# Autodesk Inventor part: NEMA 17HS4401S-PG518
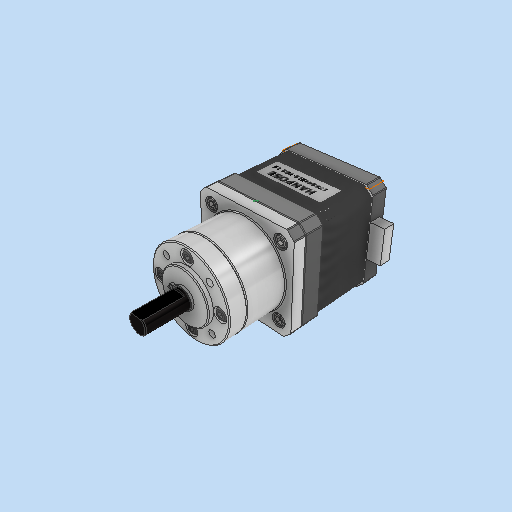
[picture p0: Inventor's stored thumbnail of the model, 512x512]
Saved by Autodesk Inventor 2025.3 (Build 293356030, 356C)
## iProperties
GlobalPropertyList: <PropertyList/>
Created: 2012-11
Part Number: NEMA 17HS4401S-PG518
Material: Rozsdamentes acél
Document SubType Name: Modeling
Designer: Romolicz Péter
Density: 8.08 g/cm^3
Mass: 635.188 g
Surface Area: 148.432 cm^2
Volume: 78.6123 cm^3
Appearance: Krómozott tengely
d0: 7.000 mm
d1: 22.000 mm
d4: 5.000 mm
d5: 31.000 mm
d6: 31.000 mm
d9: 3.000 mm
d10: 3.000 mm
d11: 3.000 mm
d12: 3.000 mm
d39: 42.000 mm
d40: 42.000 mm
d41: 135.00 deg
d42: 55.154 mm
d43: 55.154 mm
d44: 27.577 mm
d45: 27.577 mm
d46: 24.000 mm
d47: 0.00 deg
d48: 2.000 mm
d49: 0.00 deg
d50: 40,700 mm
d51: 0.00 deg
d60: -8,000 mm
d126: 25,000 mm
d127: 0.00 deg
d128: 1.000 mm
d129: 1.000 mm
d130: 1.000 mm
d131: 1.000 mm
d132: 0.500 mm
d134: 0.500 mm
d135: 0.500 mm
d136: 0.500 mm
d137: 0.500 mm
d138: 1.000 mm
d139: 1.000 mm
d140: 0.500 mm
d141: 0.00 deg
d145: 0.125 mm
d148: 56.000 ul
d150: 0.500 mm
d187: 40,000 mm
d188: 0.00 deg
d189: 47.000 mm
d190: 0.00 deg
d191: 0,600 mm
d192: 1.000 mm
d193: 0.500 mm
d196: 0.500 mm
d197: 1.200 mm
d198: 4.000 ul
d200: 1.200 mm
d205: 2.500 mm
d206: 2.500 mm
d207: 1.000 mm
d208: 0.00 deg
d209: 0.300 mm
d210: 10.000 mm
d211: 0.00 deg
d212: 10.000 mm
d213: 0.00 deg
d214: 10.000 mm
d215: 0.00 deg
d216: 10.000 mm
d217: 0.00 deg
d218: 0.200 mm
d219: 5.000 mm
d220: 0.00 deg
d221: 0.00 deg
Author: Romolicz Péter
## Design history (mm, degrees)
node "Annotazioni"
  node "Quota lineare 1" dims "d39" = 42, "d40" = 42, angle "d41" = 135 deg, "d42" = 55.154 (derived), "d43" = 55.154, "d44" = 27.577 (derived), "d45" = 27.577 (derived), "d294" = 45.7 (derived)
  node "Quota lineare 2" dims "d39" = 42, "d40" = 42, angle "d41" = 135 deg, "d42" = 55.154 (derived), "d43" = 55.154, "d44" = 27.577 (derived), "d45" = 27.577 (derived), "d297" = 42 (derived)
  node "Quota lineare 3" dims "d39" = 42, "d40" = 42, angle "d41" = 135 deg, "d42" = 55.154 (derived), "d43" = 55.154, "d44" = 27.577 (derived), "d45" = 27.577 (derived), "d300" = 42 (derived)
  node "Quota diametro 1" dims "d39" = 42, "d40" = 42, angle "d41" = 135 deg, "d42" = 55.154 (derived), "d43" = 55.154, "d44" = 27.577 (derived), "d45" = 27.577 (derived), "d302" = 36 (derived)
  node "Quota lineare 4" dims "d39" = 42, "d40" = 42, angle "d41" = 135 deg, "d42" = 55.154 (derived), "d43" = 55.154, "d44" = 27.577 (derived), "d45" = 27.577 (derived), "d305" = 18 (derived)
  node "Quota lineare 5" dims "d39" = 42, "d40" = 42, angle "d41" = 135 deg, "d42" = 55.154 (derived), "d43" = 55.154, "d44" = 27.577 (derived), "d45" = 27.577 (derived), "d308" = 2 (derived)
  node "Quota lineare 6" dims "d39" = 42, "d40" = 42, angle "d41" = 135 deg, "d42" = 55.154 (derived), "d43" = 55.154, "d44" = 27.577 (derived), "d45" = 27.577 (derived), "d311" = 24 (derived)
sketch "Sketch1"
  geometry: L1 (-15.5, 15.5)-(15.5, 15.5); L2 (15.5, 15.5)-(15.5, -15.5); L3 (15.5, -15.5)-(-15.5, -15.5); L4 (-15.5, -15.5)-(-15.5, 15.5); L5 (-21, 21)-(21, 21); L6 (21, 21)-(21, -21); L7 (21, -21)-(-21, -21); L8 (-21, -21)-(-21, 21); L9 (-21, 18)-(-18, 21); L10 (21, 18)-(18, 21); L11 (-21, -18)-(-18, -21); L12 (21, -18)-(18, -21); L13 (-21, 18)-(-21, -18); L14 (-18, -21)-(18, -21); L15 (21, -18)-(21, 18); L16 (18, 21)-(-18, 21); C1 r 3.5 at (0, 0); C2 r 11 at (0, 0); C3 r 2.5 at (0, 0); C4 r 1.5 at (-15.5, 15.5); C5 r 1.5 at (15.5, 15.5); C6 r 1.5 at (-15.5, -15.5); C7 r 1.5 at (15.5, -15.5); 5 further points
  constraints: 32 end point, 8 point on line, 7 centre point, 6 coincident, 5 parallel, 4 collinear, 4 midpoint, 4 perpendicular, 2 horizontal, 2 horizontal alignment, 2 vertical alignment, 1 concentric
  dimensions: "d0" = 7 diameter of C1; "d1" = 22 diameter of C2; "d4" = 5 diameter of C3; "d5" = 31 distance of L2.end L3.end; "d6" = 31 distance of L1.end L2.end; "d9" = 3 diameter of C4; "d10" = 3 diameter of C5; "d11" = 3 diameter of C6; "d12" = 3 diameter of C7; "d39" = 42 distance of L6.end L7.end; "d40" = 42 distance of L5.end L6.end; "d41" = 135 deg angle of L10 L6; "d42" = 55.154 distance between parallel lines of L10 L11 (derived); "d43" = 55.154 distance between parallel lines of L12 L9; "d44" = 27.577 distance from line of point (0, 0) L10 (derived); "d45" = 27.577 distance from line of point (0, 0) L12 (derived)
extrude "Extrusion1" new body sketch "Sketch1" distance "d46" = 24; taper "d47" = 0 deg; dims "d187" = 40, angle "d188" = 0 deg
extrude "Extrusion2" join sketch "Sketch1" distance "d48" = 2; taper "d49" = 0 deg
extrude "Extrusion3" join sketch "Sketch1" distance "d50" = 40.7; taper "d51" = 0 deg
workplane "Work Plane2"
sketch "Sketch4"
  geometry: L1 (-21, 18)-(-18, 21) reference; L2 (-21, 18)-(-18, 21) reference; L3 (-21, -18)-(-21, 18) reference; L4 (-18, -21)-(-21, -18) reference; L5 (18, -21)-(-18, -21) reference; L6 (21, -18)-(18, -21) reference; L7 (21, 18)-(21, -18) reference; L8 (18, 21)-(21, 18) reference; L9 (-18, 21)-(18, 21) reference; C1 r 1.5 at (-15.5, 15.5) reference; C2 r 1.5 at (-15.5, -15.5) reference; C3 r 1.5 at (15.5, 15.5) reference; C4 r 1.5 at (15.5, -15.5) reference; C5 r 11 at (0, 0) reference; 1 further point
extrude "Extrusion7" cut sketch "Sketch4" distance "d126" = 25; taper "d127" = 0 deg
sketch "Sketch5"
  geometry: L1 (-21, -18)-(-21, 18) reference; L2 (-18, -21)-(-21, -18) reference; L3 (18, -21)-(-18, -21) reference; L4 (21, -18)-(18, -21) reference; L5 (21, 18)-(21, -18) reference; L6 (18, 21)-(21, 18) reference; L7 (-18, 21)-(18, 21) reference; L8 (-21, 18)-(-18, 21) reference; L9 (-17.086, 20.5)-(-20.5, 17.086); L10 (-20.5, -17.086)-(-17.086, -20.5); L11 (-18, -21)-(-21, -18) reference; L12 (21, -18)-(18, -21) reference; L13 (18, 21)-(21, 18) reference; L14 (-21, 18)-(-18, 21) reference; L15 (20.5, -17.086)-(20.5, 17.086); L16 (17.086, 20.5)-(-17.086, 20.5); L17 (-20.5, 17.086)-(-20.5, -17.086); L18 (-17.086, -20.5)-(17.086, -20.5); L19 (17.086, -20.5)-(20.5, -17.086); L20 (20.5, 17.086)-(17.086, 20.5); C1 r 11 at (0, 0) reference; C2 r 1.5 at (15.5, -15.5) reference; C3 r 1.5 at (15.5, 15.5) reference; C4 r 1.5 at (-15.5, -15.5) reference; C5 r 1.5 at (-15.5, 15.5) reference
  constraints: 16 end point, 5 parallel
  dimensions: "d128" = 1 distance between parallel lines of L10 L2; "d131" = 1 distance between parallel lines of L8 L9; "d132" = 0.5 distance between parallel lines of L1 L17; "d134" = 0.5 distance between parallel lines of L5 L15; "d135" = 0.5 distance between parallel lines of L7 L16; "d137" = 0.5 distance between parallel lines of L18 L3; "d138" = 1 distance between parallel lines of L4 L19; "d139" = 1 distance between parallel lines of L6 L20
extrude "Extrusion8" join sketch "Sketch5" distance "d140" = 0.5; taper "d141" = 0 deg
chamfer "Chamfer1" distance "d145" = 0.125; stored, may be unused: second distance "d146" = 2, angle "d147" = 45 deg
extrude "Extrusion9" join sketch "Sketch1" distance "d189" = 47; taper "d190" = 0 deg
fillet "Fillet1" dims "d191" = 0.6
fillet "Fillet2" dims "d192" = 1
chamfer "Chamfer2" distance "d193" = 0.5; stored, may be unused: second distance "d194" = 2, angle "d195" = 45 deg
fillet "Fillet3" dims "d196" = 0.5
sketch "Sketch6" dims "d205" = 2.5
  geometry: L1 (35.502, 0)-(0, 0) reference; L2 (35.502, -7.1)-(0, -7.1) reference; C1 r 0.6 at (15.951, -2.5); C2 r 0.6 at (19.551, -2.5); 6 further points; 2 other entities
  constraints: 4 horizontal, 2 centre point, 2 horizontal alignment, 1 coincident, 1 midpoint, 1 vertical alignment, 13 other
  dimensions: "d197" = 1.2 diameter of C1; "d200" = 1.2 distance of C1.centre point (17.151, -2.5); "d206" = 2.5 distance from line of L1 point (17.751, -2.5)
  node "Schizzo - Serie rettangolare1" dims "d200" = 1.2, "d203" = 10
extrude "Extrusion10" join sketch "Sketch6" distance "d207" = 1; taper "d208" = 0 deg
fillet "Fillet4" dims "d209" = 0.3
extrude "Extrusion11" join sketch "Sketch6" distance "d210" = 10; taper "d211" = 0 deg
extrude "Extrusion12" join sketch "Sketch6" distance "d212" = 10; taper "d213" = 0 deg
extrude "Extrusion13" join sketch "Sketch6" distance "d214" = 10; taper "d215" = 0 deg
extrude "Extrusion14" join sketch "Sketch6" distance "d216" = 10; taper "d217" = 0 deg
extrude "Extrusion15" join sketch "Sketch6" distance "d218" = 0.2; taper "d220" = 0 deg; dims "d219" = 5, angle "d221" = 0 deg
sketch "Sketch11"
  geometry: L1 (20.5, 17.793)-(17.793, 20.5); L2 (20.5, 17.793)-(17.793, 20.5); L3 (2.875, 14)-(2.875, 17.769); L4 (2.875, 14)-(2.875, 17.769); L5 (-17.793, -20.5)-(17.793, -20.5); L6 (-20.5, -17.793)-(-17.793, -20.5); L7 (-20.5, -17.793)-(-17.793, -20.5); L8 (-21, 21)-(21, -21); L9 (21, 21)-(-21, -21); L10 (-2.646, 3)-(2.646, 3); L11 (2.646, 3)-(-2.646, 3); L12 (17.793, -20.5)-(20.5, -17.793); L13 (17.793, -20.5)-(20.5, -17.793); L14 (0, 15.181)-(1.023, 14.59); L15 (1.023, 14.59)-(1.023, 13.41); L16 (1.023, 13.41)-(0, 12.819); L17 (-1.022, 14.59)-(0, 15.181); L18 (-1.022, 13.41)-(-1.022, 14.59); L19 (-1.022, 13.41)-(0, 12.819); L20 (0, 12.819)-(-1.022, 13.41); L21 (-2.875, 14)-(-2.875, 17.769); L22 (-14.022, 15.5)-(-14.761, 14.22); L23 (-14.761, 16.78)-(-14.022, 15.5); L24 (-14.761, 14.22)-(-16.239, 14.22); L25 (-16.239, 16.78)-(-14.761, 16.78); L26 (-16.978, 15.5)-(-16.239, 14.22); L27 (-16.239, 14.22)-(-16.978, 15.5); L28 (-16.978, 15.5)-(-16.239, 16.78); L29 (-18.293, 49.829)-(-21, 47.122); L30 (-21, 47.122)-(-47.122, 21); L31 (-14, 2.875)-(-17.769, 2.875); L32 (-14, 2.875)-(-17.769, 2.875); L33 (-13.41, 1.023)-(-12.819, 0); L34 (-13.41, -1.022)-(-14.59, -1.022); L35 (-13.41, -1.022)-(-12.819, 0); L36 (-12.819, 0)-(-13.41, -1.022); L37 (-14.59, 1.023)-(-13.41, 1.023); L38 (-15.181, 0)-(-14.59, 1.023); L39 (-14.59, -1.022)-(-15.181, 0); L40 (-14, -2.875)-(-17.769, -2.875); L41 (-15.5, -14.022)-(-14.22, -14.761); L42 (-16.78, -14.761)-(-15.5, -14.022); L43 (-14.22, -14.761)-(-14.22, -16.239); L44 (-15.5, -16.978)-(-14.22, -16.239); L45 (-14.22, -16.239)-(-15.5, -16.978); L46 (-15.5, -16.978)-(-16.78, -16.239); L47 (-16.78, -16.239)-(-16.78, -14.761); L48 (-2.875, -14)-(-2.875, -17.769); L49 (-2.875, -14)-(-2.875, -17.769); L50 (-1.023, -13.41)-(0, -12.819); L51 (1.022, -13.41)-(1.022, -14.59); L52 (1.022, -13.41)-(0, -12.819); L53 (0, -12.819)-(1.022, -13.41); L54 (-1.023, -14.59)-(-1.023, -13.41); L55 (0, -15.181)-(-1.023, -14.59); L56 (1.022, -14.59)-(0, -15.181); L57 (2.875, -14)-(2.875, -17.769); L58 (14.022, -15.5)-(14.761, -14.22); L59 (14.761, -16.78)-(14.022, -15.5); L60 (14.761, -14.22)-(16.239, -14.22); L61 (16.978, -15.5)-(16.239, -14.22); L62 (16.239, -14.22)-(16.978, -15.5); L63 (16.978, -15.5)-(16.239, -16.78); L64 (16.239, -16.78)-(14.761, -16.78)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; C1 r 11 at (0, 0); C2 r 4 at (0, 0); C3 r 1.84 at (0, 14); C4 r 2.34 at (0, 14); C5 r 2.34 at (0, 14); C6 r 1.5 at (-9.899, 9.899); C7 r 1.5 at (-9.899, 9.899); C8 r 2.34 at (-15.5, 15.5); C9 r 2.875 at (-15.5, 15.5); C10 r 1.84 at (-14, 0); C11 r 2.34 at (-14, 0); C12 r 2.34 at (-14, 0); C13 r 1.5 at (-9.899, -9.899); C14 r 2.34 at (-15.5, -15.5); C15 r 2.875 at (-15.5, -15.5); C16 r 1.84 at (0, -14); C17 r 2.34 at (0, -14); C18 r 2.34 at (0, -14); C19 r 1.5 at (9.899, -9.899); C20 r 2.34 at (15.5, -15.5); C21 r 2.875 at (15.5, -15.5); C22 r 1.84 at (14, 0); C23 r 2.34 at (14, 0); C24 r 2.34 at (14, 0); C25 r 1.5 at (9.899, 9.899); C26 r 2.34 at (15.5, 15.5); C27 r 2.875 at (15.5, 15.5); A1 r 4.5 centre (0, 0) between (3.139, 3.224) and (3.139, -3.224); A2 r 18 centre (0, 0) between (-2.875, 17.769) and (2.875, 17.769); A3 r 4 centre (0, 0) between (0.527, 3.965) and (0.554, 3.961); A4 r 2.875 centre (0, 14) between (-2.875, 14) and (2.875, 14); A5 r 2.875 centre (0, 14) between (-2.875, 14) and (2.875, 14); A6 r 2.875 centre (-14, 0) between (-14, -2.875) and (-14, 2.875); A7 r 2.875 centre (-14, 0) between (-14, -2.875) and (-14, 2.875); A8 r 2.875 centre (0, -14) between (2.875, -14) and (-2.875, -14); A9 r 2.875 centre (0, -14) between (2.875, -14) and (-2.875, -14); A10 r 2.875 centre (14, 0) between (14, 2.875) and (14, -2.875); A11 r 2.875 centre (14, 0) between (14, 2.875) and (14, -2.875); 32 further points; 4 other entities
  constraints: 162 end point, 38 centre point, 25 coincident, 13 point on circle, 4 collinear, 3 midpoint, 2 horizontal, 1 concentric, 1 perpendicular, 1 tangent, 1 vertical, 257 other
  dimensions: "d239" = 42 distance of L8.end L9.end; "d240" = 42 distance of L9.end L8.start; "d241" = 36 diameter of A2; "d242" = 22 diameter of C1; "d245" = 360 deg dimension on A1.centre L3.end (derived)
  node "Schizzo - Serie circolare1" dims "d245" = 360 deg (derived)
extrude "Extrusion16" join sketch "Sketch11" distance "d247" = 5; taper "d248" = 0 deg
extrude "Extrusion17" join sketch "Sketch11" stored distance "d249" = 24; taper "d250" = 0 deg
extrude "Extrusion18" cut sketch "Sketch11" stored distance "d251" = 6; taper "d252" = 0 deg
extrude "Extrusion19" cut sketch "Sketch11" stored distance "d253" = 3; taper "d254" = 0 deg
extrude "Extrusion20" join sketch "Sketch11" stored distance "d255" = 3; taper "d256" = 0 deg
extrude "Extrusion21" cut sketch "Sketch11" stored distance "d257" = 1.8; taper "d258" = 0 deg
extrude "Extrusion22" cut sketch "Sketch11" distance "d259" = 5; taper "d260" = 0 deg
extrude "Extrusion23" join sketch "Sketch11" distance "d261" = 5; taper "d262" = 0 deg
extrude "Extrusion24" cut sketch "Sketch11" stored distance "d263" = 1.5; taper "d264" = 0 deg
extrude "Extrusion25" join sketch "Sketch11" stored distance "d265" = 2; taper "d266" = 0 deg
extrude "Extrusion26" join sketch "Sketch11" stored distance "d267" = 3; taper "d268" = 0 deg
extrude "Extrusion27" join sketch "Sketch11" stored distance "d269" = 15; taper "d270" = 0 deg
fillet "Fillet5" dims "d271" = 0.5
fillet "Fillet6" dims "d272" = 0.3
fillet "Fillet7" dims "d273" = 0.5
chamfer "Chamfer3" distance "d274" = 0.4; stored, may be unused: second distance "d275" = 2, angle "d276" = 45 deg
chamfer "Chamfer4" distance "d277" = 0.4; stored, may be unused: second distance "d278" = 2, angle "d279" = 45 deg
chamfer "Chamfer5" distance "d280" = 0.4; stored, may be unused: second distance "d281" = 2, angle "d282" = 45 deg
sketch "Sketch12"
  geometry: L1 (3.929, -0.75)-(6.442, -0.75); L2 (5.481, -2.833)-(6.648, -1.142); L3 (6.648, -1.142)-(5.481, -2.833); L4 (3.837, -2.941)-(5.275, -2.941); L5 (5.275, -2.941)-(3.837, -2.941); L6 (0, 0)-(-1.45, 0); L7 (3.929, 0.75)-(6.442, 0.75); L8 (5.481, 2.833)-(6.648, 1.142); L9 (6.648, 1.142)-(5.481, 2.833); L10 (3.837, 2.941)-(5.275, 2.941); L11 (5.275, 2.941)-(3.837, 2.941); C1 r 0.8 at (4.837, -1.845); C2 r 0.8 at (4.837, -1.845); C3 r 4 at (0, 0); C4 r 0.8 at (4.837, 1.845); C5 r 0.8 at (4.837, 1.845); C6 r 0.8 at (4.837, 1.845); C7 r 0.8 at (4.837, 1.845); A1 r 0.25 centre (6.442, -1) between (6.648, -1.142) and (6.442, -0.75); A2 r 0.25 centre (6.442, -1) between (6.648, -1.142) and (6.442, -0.75); A3 r 0.25 centre (5.275, -2.691) between (5.275, -2.941) and (5.481, -2.833); A4 r 0.25 centre (5.275, -2.691) between (5.275, -2.941) and (5.481, -2.833); A5 r 4.5 centre (0, 0) between (3.139, 3.224) and (3.139, -3.224); A6 r 1 centre (3.837, -3.941) between (3.837, -2.941) and (3.139, -3.224); A7 r 1 centre (3.837, -3.941) between (3.837, -2.941) and (3.139, -3.224); A8 r 4 centre (0, 0) between (3.929, -0.75) and (3.929, 0.75); A9 r 1 centre (3.837, 3.941) between (3.139, 3.224) and (3.837, 2.941); A10 r 0.25 centre (6.442, 1) between (6.442, 0.75) and (6.648, 1.142); A11 r 0.25 centre (6.442, 1) between (6.442, 0.75) and (6.648, 1.142); A12 r 0.25 centre (5.275, 2.691) between (5.481, 2.833) and (5.275, 2.941); A13 r 0.25 centre (5.275, 2.691) between (5.481, 2.833) and (5.275, 2.941); 3 further points
  constraints: 27 point on circle, 22 end point, 20 centre point, 13 symmetric about line, 5 coincident, 2 collinear, 1 horizontal, 1 parallel, 7 other
extrude "Extrusion28" join sketch "Sketch12" distance "d283" = 1; taper "d284" = 0 deg
sketch "Sketch13"
  geometry: L1 (-18, 5.4)-(-18, 28.6) reference; L2 (-18, 5.4)-(-18, 21.4); L3 (-18, 21.4)-(-17.646, 21.754); L4 (-17.646, 21.754)-(-18, 22.107); L5 (-18, 21.4)-(-18, 22.107); L6 (0, -6.4)-(0, 38.4) reference; L7 (-18, 5.4)-(18, 5.4) reference; 1 further point
  constraints: 8 end point, 4 point on line, 1 collinear, 1 perpendicular
  dimensions: "d285" = 16 distance of L2.start L2.end; "d286" = 0.5 distance of L2.end L3.end; "d287" = 135 deg angle of L2 L3
revolve "Revolution1" sketch "Sketch13" stored, may be unused: angle "d288" = 90 deg
chamfer "Chamfer6" distance "d289" = 0.4; stored, may be unused: second distance "d290" = 2, angle "d291" = 45 deg
chamfer "Smusso7" distance "d312" = 3; stored, may be unused: second distance "d313" = 2, angle "d314" = 45 deg
sketch "Schizzo14"
  geometry: L1 (2.646, -3)-(-2.646, -3); C1 r 2 at (0, 0) reference; A1 r 4 centre (0, 0) between (2.646, -3) and (-2.646, -3); 1 further point
  constraints: 2 end point, 2 point on circle, 1 centre point, 1 coincident, 1 horizontal
  dimensions: "d315" = 8 diameter of A1; "d316" = 3 distance from line of point (0, 0) L1
extrude "Estrusione29" cut sketch "Schizzo14" distance "d317" = 16; taper "d318" = 0 deg
fillet "Raccordo8" dims "d319" = 0.6
node "Piano di lavoro3"
sketch "Schizzo15"
  geometry: L1 (0.666, 7.875)-(34.837, 7.875) reference; L2 (3.264, 19)-(32.31, 19); L3 (32.31, 19)-(32.31, 7.875); L4 (32.31, 7.875)-(3.264, 7.875); L5 (3.264, 7.875)-(3.264, 19); 2 further points
  constraints: 8 end point, 2 parallel, 1 horizontal, 1 perpendicular, 1 point on line
extrude "Estrusione30" join sketch "Schizzo15" distance "d321" = 0.6; taper "d322" = 0 deg
sketch "Schizzo16"
  geometry: L1 (-10.946, 17.386)-(48.085, 17.386); L2 (48.085, 17.386)-(48.085, 2.528); L3 (48.085, 2.528)-(-10.946, 2.528); L4 (-10.946, 2.528)-(-10.946, 17.386); 1 further point
  constraints: 2 other
sketch "Schizzo17"
  geometry: L1 (0, 34.837)-(0, 0.666) reference; L2 (0, 25)-(-5, 25); L3 (-5, 25)-(-5, 10); L4 (-5, 10)-(0, 10); L5 (0, 10)-(0, 25); 2 further points
  constraints: 8 end point, 2 parallel, 1 horizontal, 1 perpendicular, 1 point on line
extrude "Estrusione31" new body sketch "Schizzo17" distance "d323" = 6; taper "d324" = 0 deg
body "Solid1"
pattern_linear "Rectangular Pattern2" dims count "d148" = 56, "d150" = 0.5
node "Projected Loop2"
node "Solido2"
other parameters: "d60" = -8, "d129" = 1, "d130" = 1, "d136" = 0.5, "d198" = 4, "d320" = -1, "d292" = 0.674 (derived), "d293" = 2.15988 (derived), "d295" = 8.30552 (derived), "d296" = 2.21127 (derived), "d298" = 5.3853 (derived), "d299" = 5.66806 (derived), "d301" = 37.63613 (derived), "d303" = 6.0013 (derived), "d304" = 9.54993 (derived), "d306" = 2.06528 (derived), "d307" = 5.64217 (derived), "d309" = 1.38493 (derived), "d310" = 3.65208 (derived)
